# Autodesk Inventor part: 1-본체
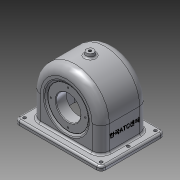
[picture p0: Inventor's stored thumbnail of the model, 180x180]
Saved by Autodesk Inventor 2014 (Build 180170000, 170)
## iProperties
Created: 2015-09
Part Number: 1-본체
Material: 알루미늄 6061
Document SubType Name: Modeling
Designer: Administrator
Density: 2.71 g/cm^3
Appearance: 알루미늄 - 평지
Mass: 736.144 g
Surface Area: 880.74 cm^2
Volume: 271.64 cm^3
Author: Administrator
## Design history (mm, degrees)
sketch "스케치1"
  geometry: L1 (-70, 52)-(70, 52); L2 (70, 52)-(70, -52); L3 (70, -52)-(-70, -52); L4 (-70, -52)-(-70, 52); 3 further points
  constraints: 8 end point, 2 midpoint, 2 parallel, 1 horizontal, 1 horizontal alignment, 1 perpendicular, 1 vertical alignment
  dimensions: "d0" = 104 distance of L1.end L2.end; "d1" = 140 distance of L2.end L3.end
extrude "돌출1" new body sketch "스케치1" distance "d2" = 7; taper "d3" = 0 deg
sketch "스케치2"
  geometry: L1 (-70, 0)-(70, 0) reference; L2 (-56, 48)-(-56, 0); L3 (-56, 0)-(56, 0); L4 (56, 0)-(56, 48); A1 r 56 centre (0, 48) between (-56, 48) and (56, 48); 2 further points
  constraints: 6 end point, 2 point on circle, 2 point on line, 2 tangent, 1 centre point, 1 midpoint, 1 perpendicular, 1 vertical, 1 vertical alignment
  dimensions: "d4" = 112 diameter of A1; "d7" = 104 dimension on A1 L1
extrude "돌출2" join sketch "스케치2" stored distance "d8" = 77; taper "d9" = 0 deg
sketch "스케치3"
  geometry: L1 (-70, 0)-(70, 0) reference; C1 r 31 at (0, -48); A1 r 56 centre (0, -48) between (-56, -48) and (56, -48) reference; 2 further points
  constraints: 1 centre point, 1 concentric, 1 midpoint, 1 vertical alignment
  dimensions: "d10" = 62 diameter of C1
sketch "스케치4"
  geometry: L1 (50, 48)-(50, 0); L2 (50, 0)-(-50, 0); L3 (-50, 0)-(-50, 48); L4 (70, 0)-(-70, 0) reference; A1 r 56 centre (0, 48) between (56, 48) and (-56, 48) reference; A2 r 50 centre (0, 48) between (50, 48) and (-50, 48); 1 further point
  constraints: 6 end point, 2 point on circle, 2 tangent, 1 centre point, 1 collinear, 1 parallel, 1 perpendicular, 1 vertical
  dimensions: "d11" = 6 radial gap between concentric circles of A1 A2
extrude "돌출3" cut sketch "스케치4" stored distance "d12" = 67; taper "d13" = 0 deg
sketch "스케치5"
  geometry: C1 r 31 at (0, -48); A1 r 56 centre (0, -48) between (-56, -48) and (56, -48) reference; 1 further point
  constraints: 1 centre point, 1 concentric
  dimensions: "d14" = 62 diameter of C1
extrude "돌출4" join sketch "스케치5" distance "d15" = 10; taper "d16" = 0 deg
sketch "스케치6"
  geometry: L1 (-10.456, 13.613)-(-10.456, 63.387); L2 (-10.456, 63.387)-(-35.544, 63.387); L3 (-35.544, 63.387)-(-35.544, 13.613); L4 (-35.544, 13.613)-(-10.456, 13.613); L5 (7, 90.5)-(7, -13.5) reference; 6 further points
  constraints: 4 midpoint, 1 horizontal alignment, 1 vertical alignment, 2 other
  dimensions: "d17" = 30 distance from line of L5 point (-23, 38.5)
feature "엠보싱1" sketch "스케치6" dims "d18" = 0.5, "d19" = 0
node "작업 평면1"
sketch "스케치7"
  geometry: C1 r 28 at (0, -48); A1 r 56 centre (0, -48) between (-56, -48) and (56, -48) reference; 1 further point
  constraints: 1 centre point, 1 concentric, 1 vertical alignment
  dimensions: "d21" = 56 diameter of C1
extrude "돌출5" join sketch "스케치7" stored distance "d22" = 10; taper "d23" = 40 deg
node "작업 평면2"
sketch "스케치8"
  geometry: C1 r 33 at (0, 48); A1 r 56 centre (0, 48) between (56, 48) and (-56, 48) reference; 1 further point
  constraints: 1 centre point, 1 concentric, 1 vertical alignment
  dimensions: "d25" = 66 diameter of C1
extrude "돌출6" cut sketch "스케치8" distance "d26" = 3; taper "d27" = 50 deg
hole "구멍1" diameter "d30" = 40; stored, may be unused: countersink angle "d34" = 90 deg, drill point angle "d36" = 0 deg; dims "d28" = 10, "d29" = 10, "d31" = 6, "d32" = 4, "d33" = 2, "d35" = 8
fillet "모깎기1" dims "d37" = 7
fillet "모깎기2" dims "d38" = 14
fillet "모깎기3" dims "d39" = 9
sketch "스케치9" dims "d11" = 6, "d21" = 56
  geometry: L1 (0, 0)-(62, 0)
  constraints: 2 end point, 1 horizontal
  dimensions: "d40" = 62 distance of L1.start L1.end
hole "구멍2" sketch "스케치9" at (62, 0) diameter "d41" = 5; stored, may be unused: countersink angle "d45" = 90 deg, drill point angle "d47" = 0 deg; dims "d42" = 6, "d43" = 4, "d44" = 2, "d46" = 8
fillet "모깎기4" dims "d63" = 3
chamfer "모따기1" distance "d64" = 1; stored, may be unused: second distance "d65" = 2, angle "d66" = 45 deg
sketch "스케치10"
  geometry: 1 further point
node "작업 평면3"
sketch "스케치11"
  geometry: C1 r 6 at (0, 0); 1 further point
  constraints: 1 centre point, 1 coincident
  dimensions: "d68" = 12 diameter of C1
extrude "돌출7" join sketch "스케치11" stored distance "d69" = 3; taper "d70" = 10 deg
fillet "모깎기5" dims "d71" = 3
hole "구멍3" diameter "d74" = 4.459; stored, may be unused: countersink angle "d78" = 90 deg, drill point angle "d80" = 0 deg; dims "d75" = 15, "d76" = 4, "d77" = 2, "d79" = 8, "d106" = 10, "d107" = 10
fillet "모깎기6" dims "d81" = 0.5
sketch "스케치12"
  geometry: L1 (0, 0)-(0, 28); L2 (63, -48)-(-63, -48) reference; 2 further points
  constraints: 2 end point, 1 midpoint, 1 vertical, 1 vertical alignment
  dimensions: "d82" = 28 distance of L1.start L1.end; "d83" = 48 distance from line of L2 L1.start
hole "구멍4" sketch "스케치12" at (0, 28) diameter "d84" = 2.621; stored, may be unused: countersink angle "d88" = 90 deg, drill point angle "d90" = 120 deg; dims "d85" = 7, "d86" = 4, "d87" = 2, "d89" = 9
sketch "스케치13"
  geometry: L1 (0, 0)-(0, -24); L2 (-63, 48)-(63, 48) reference; 2 further points
  constraints: 2 end point, 1 midpoint, 1 vertical, 1 vertical alignment
  dimensions: "d94" = 48 distance from line of L2 L1.start; "d95" = 24 distance of L1.start L1.end
hole "구멍5" sketch "스케치13" at (0, -24) diameter "d96" = 2.621; stored, may be unused: countersink angle "d100" = 90 deg, drill point angle "d102" = 120 deg; dims "d97" = 6, "d98" = 4, "d99" = 2, "d101" = 8
node "솔리드1"
pattern_linear "직사각형 패턴1" dims "d50" = 124
pattern_linear "직사각형 패턴2" dims "d53" = 44, "d56" = 124
pattern_linear "직사각형 패턴3" dims "d59" = 44, "d62" = 124
pattern_circular "원형 패턴1" dims angle "d92" = 360 deg
pattern_circular "원형 패턴2" dims angle "d104" = 360 deg
other parameters: "d20" = 15, "d24" = -3
